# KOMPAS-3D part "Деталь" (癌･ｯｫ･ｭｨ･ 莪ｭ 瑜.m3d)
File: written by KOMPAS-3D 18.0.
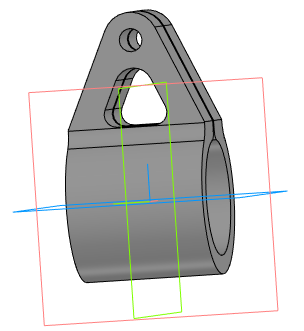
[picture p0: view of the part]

Document properties: Автор: Пользователь Windows; Полное имя файла: F:\Модели\Мех детали\Велосипед\Крепление фонаря\2\Крепление фонаря.m3d

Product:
- Part/product: Деталь
    Масса: 0.12994

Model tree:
1. Эскиз:1
2. Элемент выдавливания:1
     Расстояние 1 = 30
3. Эскиз:2
4. Элемент выдавливания:2
     Расстояние 1 = 40
5. Эскиз:3
6. Элемент выдавливания:3
     Расстояние 1 = 50
7. Скругление:1  (with: Элемент выдавливания:3)
     Радиус = 2
8. Скругление:2  (with: Элемент выдавливания:1)
     Радиус = 5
